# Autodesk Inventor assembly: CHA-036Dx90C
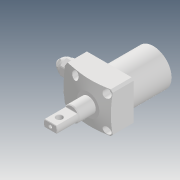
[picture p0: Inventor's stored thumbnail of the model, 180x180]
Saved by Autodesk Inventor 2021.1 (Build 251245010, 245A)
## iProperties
Created: 2019-12
Part Number: CHA-036Dx90C
Description: STEP AP203
Document SubType Name: Assembly
Designer: user
Title: CHA-036Dx90C.STEP
Revision Number: ÈÎºÎ
Sending System: SolidWorks 2017
Preprocessor: SwSTEP 2.0
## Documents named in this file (5)
- D:\Vault_2016\Projekty\Clamptek\Hydraulic\CHA\CHA\CHA-036\Inventor\CHA-036Dx90C\CHA-036Dx90C.iam
- D:\Vault_2016\Projekty\Clamptek\Hydraulic\CHA\CHA\CHA-036\Inventor\CHA-036Dx90C\CHA-036C±¾Ìå.ipt
- D:\Vault_2016\Projekty\Clamptek\Hydraulic\CHA\CHA\CHA-036\Inventor\CHA-036Dx90C\CZL10µ÷ËÙ·§.ipt
- D:\Vault_2016\Projekty\Clamptek\Hydraulic\CHA\CHA\CHA-036\Inventor\CHA-036Dx90C\G1-8¶ÂÍ·.ipt
- D:\Vault_2016\Projekty\Clamptek\Hydraulic\CHA\CHA\CHA-036\Inventor\CHA-036Dx90C\CHA-036D(Ë«±Û£©»îÈû¸Ë_1.ipt
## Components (4 placed, 4 different names)
1. CHA-036C±¾Ìå_1
2. CZL10µ÷ËÙ·§_2
3. G1-8¶ÂÍ·_3
4. CHA-036D(Ë«±Û£©»îÈû¸Ë_1_4
